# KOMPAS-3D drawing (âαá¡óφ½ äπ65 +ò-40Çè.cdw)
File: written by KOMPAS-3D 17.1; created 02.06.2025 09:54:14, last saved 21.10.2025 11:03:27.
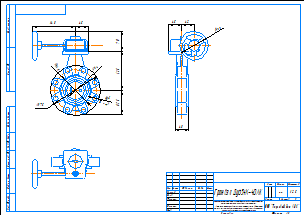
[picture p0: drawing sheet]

Sheet 1: A3, landscape

Title block, sheet 1: name: Гранвэл Ду65+Х-40АК; material: Внимание! Данный продукт является объектом авторского права ООО «Торговый Дом АДЛ». / Запрещается изменение, копирование, распространение / (в том числе путем копирования на другие сайты и ресурсы в Интернете) / или любое иное использование информации и объектов без предварительного / согласия правообладателя (ООО «Торговый Дом АДЛ»).; sheets: 1; organisation: ООО "Торговый дом АДЛ"; sheet format: A3; stored path: \\adlc.lan\data\АДЛ_ПКД\3D-модели\ADL production\Вентили ГРАНВЕНТ\KV45 Ру 40 с приводами Смартгир AZ\KOMPAS 3D\Гранвэл Ду80 +Х-40К.cdw

Views: Вид 1, Слева, Проекционный вид 3, Проекционный вид 4
Referenced files in \\adlc.lan\data\АДЛ_ПКД\3D-модели\ADL production\Дисковые поворотные затворы ГРАНВЭЛ\с резьбовыми проушинами с редуктором Ру16\KOMPAS 3D\: Гранвэл Ду80 РП Ру16 + Х-40К.m3d
Referenced files in \\adlc.lan\data\АДЛ_ПКД\3D-модели\ADL production\Дисковые поворотные затворы ГРАНВЭЛ\с резьбовыми проушинами с китайским редуктором Ру 16\KOMPAS 3D\: Гранвэл Ду65 РП Ру16 + X-40 AK.m3d
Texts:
  Andrey
  АДЛ
  Сборка
Dimensions and other numbers on the sheet: 64; 145; 16; 8 отв.; 148; 45; 175; 70; 135; 82,5; 48; 100; 42; 1:2,5; 1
